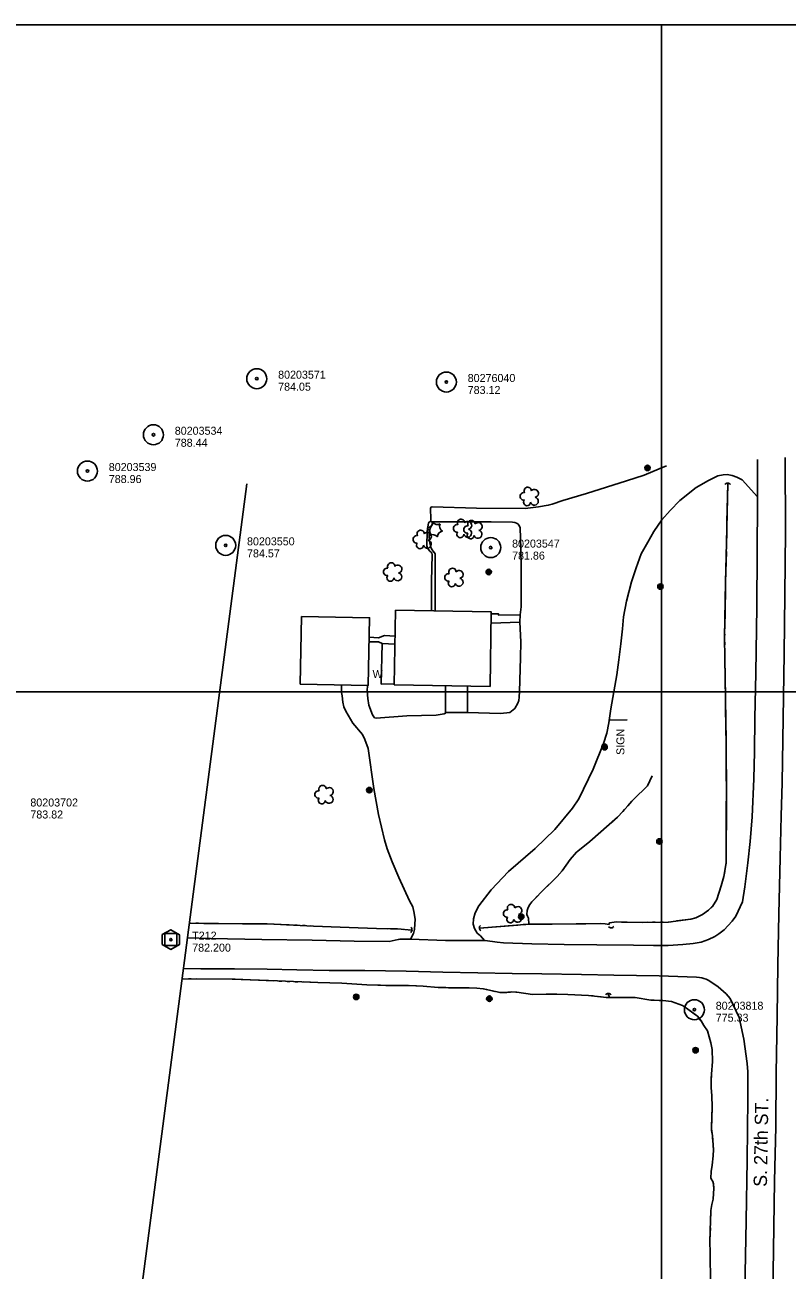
# Model space of a CAD drawing. Extents: x 591954 to 597000, y 198576 to 213500.
# Drawn here: x 593523 to 594094, y 212566 to 213500 of the extents above; entities that cross this region are included whole.
import ezdxf

# ---------------------------------------------------------------- set-up
doc = ezdxf.new("R2010")
doc.units = 0
for name, color, linetype in [('1', 7, 'Continuous'), ('Level 10', 7, 'Continuous'), ('Level 11', 7, 'Continuous'), ('Level 12', 7, 'Continuous'), ('Level 14', 7, 'Continuous'), ('Level 15', 7, 'Continuous'), ('Level 17', 7, 'Continuous'), ('Level 18', 7, 'Continuous'), ('Level 19', 7, 'Continuous'), ('Level 29', 7, 'Continuous'), ('Level 4', 7, 'Continuous'), ('Level 5', 7, 'Continuous'), ('Level 6', 7, 'Continuous')]:
    doc.layers.add(name, color=color, linetype=linetype)

msp = doc.modelspace()

# ---------------------------------------------------------------- linework, layer by layer
at = {"layer": 'Level 10'}
for p, q in [((593000, 213500), (595000, 213500)), ((594000, 212000), (594000, 213500)), ((593000, 213000), (595000, 213000))]:
    msp.add_line(p, q, dxfattribs=at)
at = {"layer": 'Level 11'}
for points in [[(594071.8, 213146.24), (594071.99, 213174.06)], [(594092.68, 213175.51), (594092.9, 213119.81), (594092.29, 213072.65), (594091.97, 213028.51), (594090.27, 212931.76), (594089.7, 212906.93), (594088.86, 212875.4), (594087.84, 212833.27), (594087.14, 212794.98), (594086.66, 212756.81), (594085.93, 212713.94), (594085.53, 212673.64), (594084.73, 212633.12), (594084.11, 212598.75), (594083.6, 212564.55), (594083.15, 212537.46), (594082.82, 212511.46), (594081.98, 212463.34), (594080.88, 212411.88), (594080.18, 212370.87), (594079.33, 212335.57), (594078.5, 212299.63), (594077.69, 212261.21)], [(593867.34, 212813.52), (593867.74, 212813.52), (593876.85, 212812.15), (593881.45, 212811.68), (593902.84, 212810.93), (593926.97, 212810.5), (593951.36, 212810.27), (593979.06, 212809.93), (593993.98, 212809.78), (594004.98, 212809.74), (594016, 212810.56), (594023.64, 212811.19), (594029.62, 212812.3), (594035.15, 212814.31), (594040, 212816.46), (594042.92, 212818.49), (594046.81, 212821.57), (594052.9, 212827.99), (594055.72, 212831.67), (594060.58, 212842.45), (594062.44, 212853.72), (594064.74, 212871.68), (594066.41, 212887.58), (594067.84, 212906.27), (594069.16, 212934.57), (594069.56, 212954.94), (594069.92, 212980.15), (594070.59, 213013.89), (594071.47, 213063.73), (594071.73, 213103.98), (594071.78, 213143.2), (594071.8, 213146.24)], [(593644.66, 212815.5), (593661.85, 212815.09), (593700.41, 212814.29), (593738.06, 212813.73), (593769.47, 212813.01), (593795.9, 212812.79), (593802.64, 212814.18), (593804.04, 212814.52), (593805.93, 212814.57), (593811.71, 212814.48)], [(593811.71, 212814.48), (593837.94, 212813.49), (593867.34, 212813.52)], [(594062.39, 212551.08), (594063.31, 212603.36), (594064.13, 212648.72), (594064.57, 212694.79), (594064.68, 212709.98), (594064.57, 212715.11), (594064.04, 212721.15), (594061.78, 212739.41), (594058.15, 212755.76), (594051.39, 212769.97), (594048.32, 212773.56), (594042.39, 212778.73), (594037.01, 212782.5), (594034.82, 212783.72), (594033.43, 212784.35), (594031.76, 212785.06), (594030.25, 212785.44), (594028.4, 212785.7), (594026.26, 212785.86), (593998.27, 212786.99), (593964.23, 212787.37), (593940.05, 212787.94), (593910.2, 212788.39), (593888, 212788.76), (593862.21, 212789.1), (593836.02, 212789.75), (593808.47, 212790.37), (593777.54, 212790.97), (593750.93, 212791.08), (593726.61, 212791.42), (593704.37, 212791.9), (593679.9, 212792.13), (593654.64, 212792.32), (593641.66, 212792.57)]]:
    msp.add_lwpolyline(points, dxfattribs=at)
at = {"layer": 'Level 12'}
for points in [[(593730.19, 213056.46), (593729.15, 213005.79), (593780.14, 213004.74), (593781.18, 213055.41), (593730.19, 213056.46)], [(593799.66, 213005.1), (593871.45, 213003.94), (593872.35, 213059.88), (593800.57, 213061.04), (593799.66, 213005.1)], [(593893.92, 213057.76), (593877.77, 213057.53), (593877.73, 213058.42), (593872.33, 213058.35)]]:
    msp.add_lwpolyline(points, dxfattribs=at)
at = {"layer": 'Level 14'}
msp.add_lwpolyline([(593974.27, 212978.92), (593960.4, 212978.7)], dxfattribs=at)
for centre, radius in [((593989.45, 213167.79), 2.02), ((593989.45, 213167.8), 1.52), ((593989.46, 213167.76), 1.01), ((593989.46, 213167.77), 0.502), ((593870.46, 213089.79), 2.02), ((593870.46, 213089.8), 1.52), ((593870.47, 213089.76), 1.01), ((593870.47, 213089.77), 0.502), ((593999.18, 213078.85), 2.02), ((593999.17, 213078.86), 1.52), ((593999.18, 213078.82), 1.01), ((593999.18, 213078.83), 0.502), ((593957.21, 212958.73), 2.02), ((593957.29, 212958.34), 2.02), ((593957.21, 212958.74), 1.52), ((593957.28, 212958.35), 1.52), ((593957.22, 212958.7), 1.01), ((593957.29, 212958.31), 1.01), ((593957.22, 212958.71), 0.502), ((593957.29, 212958.32), 0.502), ((593780.94, 212926.21), 2.02), ((593780.94, 212926.22), 1.52), ((593780.95, 212926.18), 1.01), ((593780.95, 212926.19), 0.502), ((593998.4, 212887.74), 2.02), ((593998.4, 212887.76), 1.52), ((593998.41, 212887.72), 1.01), ((593998.41, 212887.73), 0.502), ((593894.79, 212831.3), 2.02), ((593894.78, 212831.32), 1.52), ((593894.79, 212831.28), 1.01), ((593894.79, 212831.29), 0.502), ((593771.11, 212771.19), 2.02), ((593771.1, 212771.2), 1.52), ((593771.11, 212771.16), 1.01), ((593771.11, 212771.17), 0.502), ((593870.92, 212769.84), 2.02), ((593870.92, 212769.86), 1.52), ((593870.92, 212769.82), 1.01), ((593870.93, 212769.83), 0.502), ((594025.48, 212731.21), 2.02), ((594025.48, 212731.23), 1.52), ((594025.48, 212731.19), 1.01), ((594025.49, 212731.2), 0.502)]:
    msp.add_circle(centre, radius, dxfattribs=at)
at = {"layer": 'Level 15'}
msp.add_lwpolyline([(593800.16, 213035.73), (593790.51, 213036.24), (593789.93, 213005.78), (593799.67, 213005.81)], dxfattribs=at)
for centre, start, end in [((594049.57, 213153.87), 35.87943, 142.11899), ((593810.45, 212821.47), 304.27944, 50.519), ((593865.88, 212822.81), 128.97943, 235.21899), ((593962.13, 212825.42), 220.27943, 326.51899), ((593960.12, 212771.21), 37.27942, 143.51898)]:
    msp.add_arc(centre, 2.5, start, end, dxfattribs=at)
at = {"layer": 'Level 17'}
for points in [[(593827.16, 213128.06), (593827.14, 213129.23), (593826.89, 213137.72), (593827.33, 213138.43), (593828.08, 213138.55), (593861.39, 213137.69), (593897.8, 213137.49), (593907.78, 213138.74), (593915.09, 213139.8), (593918.09, 213140.54), (593926.03, 213143.31), (593943.8, 213148.67), (593973.82, 213158.03), (593986.88, 213162.47), (593998.08, 213167.05), (594003.62, 213169.36)], [(593827.16, 213128.06), (593825.33, 213126.65), (593824.24, 213120.17), (593824.03, 213109.33), (593824.58, 213107.9), (593825.02, 213106.9), (593826.61, 213105.27), (593827.42, 213104.58), (593827.86, 213103.9), (593828.16, 213102.78), (593827.51, 213082.56), (593827.66, 213060.6)], [(593830.33, 213060.56), (593830.18, 213075.76), (593830.29, 213102.89), (593830.19, 213103.5), (593829.8, 213104.21), (593828.71, 213105.52), (593828.09, 213106.49), (593827.16, 213108.15), (593825.96, 213112.85), (593825.82, 213116.79), (593825.9, 213120.4), (593826.23, 213121.72), (593826.83, 213123.16), (593829.24, 213127.37)], [(593829.24, 213127.37), (593827.41, 213127.32), (593827.16, 213128.06)], [(593893.77, 213052.17), (593893.92, 213057.76), (593894.71, 213063.54), (593894.76, 213070.24), (593894.66, 213093.79), (593894.49, 213107.14), (593893.97, 213122.83), (593893.18, 213124.69), (593892.18, 213125.95), (593891.3, 213126.47), (593889.97, 213127), (593888.19, 213127.04), (593872.32, 213127.37), (593853.77, 213127.35), (593829.24, 213127.37)], [(593854.42, 212984.34), (593879.25, 212983.72), (593886.25, 212984.34), (593890.06, 212987.48), (593892.15, 212991.31), (593892.92, 212993.48), (593893.35, 212995.81), (593893.61, 213000.09), (593894.33, 213025.54), (593894.47, 213037.35), (593893.77, 213052.17)], [(593872.21, 213051.35), (593893.77, 213052.17)], [(593790.51, 213036.24), (593787.88, 213037.35), (593780.81, 213037.34)], [(593780.88, 213040.98), (593787.86, 213040.52), (593792.32, 213042.2), (593800.26, 213041.73)], [(593811.71, 212814.48), (593814.11, 212818.77), (593814.83, 212821.66), (593815.15, 212825.87), (593815.23, 212829.32), (593814.59, 212833.9), (593813.47, 212838.71), (593810.98, 212843.19), (593802.99, 212860.8), (593798, 212872.56), (593794.24, 212882.12), (593792.37, 212889.04), (593787.94, 212907.96), (593784.24, 212927.39), (593780.07, 212957.37), (593777.61, 212964.16), (593775.82, 212968), (593768.68, 212976.4), (593763.45, 212985.34), (593761.9, 212988.69), (593760.97, 212992.23), (593760.47, 212996.96), (593760.2, 212999.31), (593760.21, 213005.15)], [(593779.53, 213004.75), (593779.42, 213000.62), (593779.82, 212995.02), (593780.68, 212989.87), (593783.45, 212982.68), (593784.23, 212981.18), (593784.93, 212980.46), (593786.05, 212980.23), (593809.06, 212982.03), (593831.04, 212982.31), (593837.11, 212983.31), (593838.08, 212983.99), (593838.64, 212984.43)], [(593838.64, 212984.43), (593838.03, 212984.43), (593837.96, 213004.48)], [(593854.42, 212984.34), (593854.46, 213004.22)], [(593838.64, 212984.43), (593853.89, 212984.35), (593854.42, 212984.34)]]:
    msp.add_lwpolyline(points, dxfattribs=at)
at = {"layer": 'Level 18'}
for centre, radius, start, end in [((593896.71, 213146.51), 2.78, 78.07156, 279.08261), ((593899.71, 213150.59), 2.78, 1.39455, 209.16754), ((593904.75, 213148.73), 2.97, 278.42366, 139.65754), ((593899.17, 213142.11), 2.61, 140.77971, 358.71232), ((593904.64, 213142.88), 2.97, 196.07448, 79.04774), ((593849.7, 213126.6), 2.78, 1.39455, 209.16754), ((593819.47, 213118.34), 2.78, 1.39455, 209.16754), ((593824, 213127.1), 4.3, 275.21132, 0.97623), ((593822.31, 213119.05), 4.3, 335.21132, 60.97623), ((593831.82, 213129.65), 4.3, 215.21132, 300.97623), ((593836.24, 213116.11), 4.3, 95.21133, 180.97624), ((593837.94, 213124.16), 4.3, 155.21133, 240.97624), ((593846.7, 213122.52), 2.78, 78.07156, 279.08261), ((593849.16, 213118.12), 2.61, 140.77971, 358.71232), ((593854.46, 213121.63), 2.78, 78.07156, 279.08261), ((593854.63, 213118.89), 2.97, 196.07448, 79.04774), ((593854.74, 213124.74), 2.97, 278.42366, 139.65754), ((593857.46, 213125.7), 2.78, 1.39455, 209.16754), ((593862.39, 213117.99), 2.97, 196.07448, 79.04774), ((593862.5, 213123.85), 2.97, 278.42366, 139.65754), ((593816.47, 213114.26), 2.78, 78.07156, 279.08261), ((593818.93, 213109.86), 2.61, 140.77971, 358.71232), ((593824.4, 213110.62), 2.97, 196.07448, 79.04774), ((593824.51, 213116.48), 2.97, 278.42366, 139.65754), ((593828.42, 213113.56), 4.3, 35.21133, 120.97624), ((593856.92, 213117.23), 2.61, 140.77971, 358.71232), ((593794.33, 213089.84), 2.78, 78.07156, 279.08261), ((593797.33, 213093.91), 2.78, 1.39455, 209.16754), ((593802.37, 213092.06), 2.97, 278.42366, 139.65754), ((593843.27, 213089.81), 2.78, 1.39455, 209.16754), ((593796.79, 213085.44), 2.61, 140.77971, 358.71232), ((593802.26, 213086.2), 2.97, 196.07448, 79.04774), ((593840.27, 213085.73), 2.78, 78.07156, 279.08261), ((593842.73, 213081.33), 2.61, 140.77971, 358.71232), ((593848.2, 213082.1), 2.97, 196.07448, 79.04774), ((593848.31, 213087.95), 2.97, 278.42366, 139.65754), ((593742.86, 212922.94), 2.78, 78.07156, 279.08261), ((593745.86, 212927.01), 2.78, 1.39455, 209.16754), ((593750.9, 212925.15), 2.97, 278.42366, 139.65754), ((593745.32, 212918.54), 2.61, 140.77971, 358.71232), ((593750.79, 212919.3), 2.97, 196.07448, 79.04774), ((593887.2, 212837.79), 2.78, 1.39455, 209.16754), ((593884.2, 212833.71), 2.78, 78.07156, 279.08261), ((593886.66, 212829.32), 2.61, 140.77971, 358.71232), ((593892.13, 212830.08), 2.97, 196.07448, 79.04774), ((593892.24, 212835.93), 2.97, 278.42366, 139.65754)]:
    msp.add_arc(centre, radius, start, end, dxfattribs=at)
at = {"layer": 'Level 19'}
for points in [[(594049.59, 213156.18), (594048.74, 213111.67), (594048.03, 213082.12), (594047.27, 213040.69), (594048.02, 212994.11), (594048.31, 212963.43), (594048.56, 212920.3), (594048.37, 212871.67), (594046.77, 212861.49), (594044.76, 212854.41), (594041.46, 212844.33), (594038.08, 212838.99), (594035.11, 212836.12), (594030.72, 212832.88), (594025.74, 212830.56), (594021.81, 212829.51), (594004.85, 212827.24), (593985.72, 212827.05), (593974.28, 212827.1), (593969.89, 212827.25), (593966.13, 212827.37), (593960.94, 212826.65), (593960.77, 212825.5)], [(594049.59, 213156.18), (594049.04, 213127.19)], [(594048.96, 213123.19), (594048.92, 213121.19)], [(594048.72, 213111.19), (594048.68, 213109.19)], [(594048.84, 213117.19), (594048.8, 213115.19)], [(594048.58, 213105.19), (594048.03, 213082.12), (594047.92, 213076.2)], [(594047.92, 213076.2), (594047.39, 213047.2)], [(594047.31, 213043.2), (594047.28, 213041.21)], [(594047.32, 213037.21), (594047.35, 213035.21)], [(594047.42, 213031.21), (594047.45, 213029.21)], [(594047.52, 213025.21), (594047.99, 212996.21)], [(594047.99, 212996.21), (594048.02, 212994.11), (594048.27, 212967.21)], [(594048.31, 212963.21), (594048.32, 212961.21)], [(594048.34, 212957.21), (594048.35, 212955.21)], [(594048.38, 212951.21), (594048.39, 212949.21)], [(594048.41, 212945.21), (594048.56, 212920.3), (594048.54, 212916.21)], [(593992.96, 212936.82), (593989.38, 212929.45), (593986.34, 212926.35), (593982.05, 212922.18), (593977.81, 212917.97), (593974.62, 212914.5), (593970.97, 212910.16), (593967.06, 212905.94), (593946.14, 212887.62), (593936.2, 212879.65), (593931.48, 212874.15), (593925.51, 212865.73), (593921.74, 212861.38), (593910.27, 212850.21), (593905.66, 212845.55), (593902.82, 212842.4), (593901.3, 212840.34), (593899.94, 212838.11), (593899.15, 212835.94), (593898.99, 212833.08), (593899.6, 212831.63), (593900.19, 212830.29), (593900.55, 212825.7)], [(593974.76, 212914.66), (593977.81, 212917.97), (593982.05, 212922.18), (593986.34, 212926.35), (593989.38, 212929.45), (593992.96, 212936.82)], [(594048.54, 212916.21), (594048.43, 212887.21)], [(593966.79, 212905.7), (593967.06, 212905.94), (593968.17, 212907.14)], [(593970.89, 212910.07), (593970.97, 212910.16), (593972.18, 212911.6)], [(593937.12, 212880.39), (593946.14, 212887.62), (593959.26, 212899.11)], [(593962.27, 212901.74), (593963.78, 212903.06)], [(593918.52, 212858.25), (593921.74, 212861.38), (593925.51, 212865.73), (593931.48, 212874.15), (593936.2, 212879.65), (593937.12, 212880.39)], [(594048.39, 212877.21), (594048.39, 212875.21)], [(594048.42, 212883.21), (594048.41, 212881.21)], [(594048.3, 212871.22), (594047.99, 212869.24)], [(594047.37, 212865.29), (594046.77, 212861.49), (594044.76, 212854.41), (594041.46, 212844.33), (594038.08, 212838.99), (594037.45, 212838.39)], [(593909.93, 212849.87), (593910.27, 212850.21), (593911.36, 212851.27)], [(593914.22, 212854.06), (593915.66, 212855.46)], [(593900.55, 212825.7), (593900.19, 212830.29), (593899.6, 212831.63), (593898.99, 212833.08), (593899.15, 212835.94), (593899.94, 212838.11), (593901.3, 212840.34), (593902.82, 212842.4), (593903.03, 212842.63)], [(593905.71, 212845.6), (593907.12, 212847.02)], [(594037.45, 212838.39), (594035.11, 212836.12), (594030.72, 212832.88), (594025.74, 212830.56), (594021.81, 212829.51), (594011.19, 212828.09)], [(593646.09, 212826.49), (593667.8, 212826.09), (593704.44, 212825.96), (593739.17, 212824.3), (593759.14, 212823.55), (593786.45, 212822.47), (593796.77, 212822.13), (593802.11, 212822.1), (593812.81, 212821.24)], [(593646.87, 212826.48), (593646.09, 212826.49)], [(593652.86, 212826.37), (593650.86, 212826.4)], [(593685.86, 212826.02), (593667.8, 212826.09), (593656.86, 212826.29)], [(593714.85, 212825.46), (593704.44, 212825.96), (593685.86, 212826.02)], [(593720.84, 212825.17), (593718.84, 212825.27)], [(593726.84, 212824.89), (593724.84, 212824.98)], [(593732.83, 212824.6), (593730.83, 212824.7)], [(593765.8, 212823.29), (593759.14, 212823.55), (593739.17, 212824.3), (593736.83, 212824.41)], [(593794.78, 212822.2), (593786.45, 212822.47), (593765.8, 212823.29)], [(593800.78, 212822.11), (593798.78, 212822.12)], [(593806.77, 212821.73), (593804.77, 212821.89)], [(593812.75, 212821.25), (593810.75, 212821.41)], [(593863.45, 212822.78), (593900.55, 212825.7), (593917.99, 212825.71), (593953.88, 212826.1), (593957.75, 212825.9), (593959.29, 212825.66), (593960.77, 212825.5)], [(593892.37, 212825.05), (593863.45, 212822.78)], [(593898.35, 212825.52), (593896.35, 212825.37)], [(593904.34, 212825.7), (593902.34, 212825.7)], [(593910.34, 212825.7), (593908.34, 212825.7)], [(593943.34, 212825.98), (593917.99, 212825.71), (593914.34, 212825.7)], [(593960.77, 212825.5), (593959.29, 212825.66), (593957.75, 212825.9), (593953.88, 212826.1), (593943.34, 212825.98)], [(593960.84, 212826.02), (593960.77, 212825.5)], [(593989.24, 212827.09), (593985.72, 212827.05), (593974.28, 212827.1), (593969.89, 212827.25), (593966.13, 212827.37), (593960.94, 212826.65), (593960.84, 212826.02)], [(593995.24, 212827.15), (593993.24, 212827.13)], [(594001.24, 212827.21), (593999.24, 212827.19)], [(594007.22, 212827.56), (594005.24, 212827.3)], [(593640.65, 212784.78), (593678.26, 212784.56), (593712.01, 212783.11), (593742.36, 212781.91), (593760.45, 212781.5), (593778.98, 212780.17), (593795.3, 212779.71), (593810.33, 212779.68), (593821.23, 212779.22), (593832.66, 212778.25), (593838.19, 212778.12), (593855.7, 212777.94), (593861.48, 212777.79), (593866.3, 212777.3), (593879.03, 212774.39), (593884.05, 212774.6), (593887.4, 212774.88), (593891.6, 212774.78), (593903.14, 212773.04), (593913.58, 212773.22), (593916.91, 212773.31), (593921.54, 212773.31), (593929.66, 212773.09), (593945.14, 212772.32), (593949.74, 212771.8), (593956.35, 212771.02), (593959.62, 212770.63), (593960.87, 212770.68), (593975.67, 212770.71), (593980.26, 212770.63), (593992.03, 212768.65), (593994.5, 212768.61), (593998.12, 212768.52), (594000.87, 212768.52), (594007.45, 212767.85), (594015.77, 212764.84), (594018.78, 212762.66), (594027, 212756.62), (594029.56, 212753.14), (594031.76, 212749.79), (594034.34, 212745.73), (594037, 212736.65), (594037.84, 212731.74), (594038.11, 212722.7), (594037.45, 212713.2), (594037.05, 212707.74), (594037.22, 212702.92), (594037.57, 212697.13), (594037.99, 212688.51), (594037.31, 212672.15), (594038.06, 212666.93), (594038.82, 212656.85), (594038.77, 212651.99), (594037.84, 212644.98), (594037.18, 212640.32), (594036.94, 212635.31), (594038.77, 212632.19), (594039.06, 212627.79), (594038.57, 212619.55), (594037.66, 212615.59), (594036.9, 212611.06), (594036.54, 212595.69), (594036.17, 212587.51), (594036.33, 212579.57)], [(593640.65, 212784.78), (593641.36, 212784.78)], [(593645.36, 212784.76), (593647.36, 212784.74)], [(593651.36, 212784.72), (593678.26, 212784.56), (593680.36, 212784.47)], [(593680.36, 212784.47), (593709.33, 212783.23)], [(593713.33, 212783.06), (593715.33, 212782.98)], [(593719.33, 212782.82), (593721.32, 212782.74)], [(593725.32, 212782.59), (593727.32, 212782.51)], [(593731.32, 212782.35), (593742.36, 212781.91), (593760.3, 212781.51)], [(593760.3, 212781.51), (593760.45, 212781.5), (593778.98, 212780.17), (593789.25, 212779.88)], [(593793.25, 212779.77), (593795.25, 212779.71)], [(593799.25, 212779.7), (593801.25, 212779.7)], [(593805.25, 212779.69), (593807.25, 212779.68)], [(593811.25, 212779.64), (593821.23, 212779.22), (593832.66, 212778.25), (593838.19, 212778.12), (593840.2, 212778.1)], [(593840.2, 212778.1), (593855.7, 212777.94), (593861.48, 212777.79), (593866.3, 212777.3), (593869.1, 212776.66)], [(593872.99, 212775.77), (593874.95, 212775.32)], [(593878.84, 212774.43), (593879.03, 212774.39), (593880.84, 212774.46)], [(593884.83, 212774.66), (593886.83, 212774.83)], [(593890.82, 212774.8), (593891.6, 212774.78), (593903.14, 212773.04), (593913.58, 212773.22), (593916.91, 212773.31), (593919.69, 212773.31)], [(593919.69, 212773.31), (593921.54, 212773.31), (593929.66, 212773.09), (593945.14, 212772.32), (593948.64, 212771.92)], [(593952.62, 212771.46), (593954.6, 212771.22)], [(593958.58, 212770.75), (593959.62, 212770.63), (593960.57, 212770.67)], [(593960.06, 212773.42), (593960.87, 212770.68)], [(593960.06, 212773.42), (593960.87, 212770.68)], [(593964.57, 212770.69), (593966.57, 212770.69)], [(593970.57, 212770.7), (593975.67, 212770.71), (593980.26, 212770.63), (593992.03, 212768.65), (593994.5, 212768.61), (593998.12, 212768.52), (593999.4, 212768.52)], [(593999.4, 212768.52), (594000.87, 212768.52), (594007.45, 212767.85), (594015.77, 212764.84), (594018.78, 212762.66), (594025.51, 212757.71)], [(594028.28, 212754.89), (594029.46, 212753.28)], [(594031.66, 212749.94), (594031.76, 212749.79), (594032.74, 212748.25)], [(594034.63, 212744.76), (594035.19, 212742.84)], [(594036.31, 212739), (594037, 212736.65), (594037.84, 212731.74), (594038.11, 212722.7), (594037.45, 212713.2), (594037.23, 212710.21)], [(594037.23, 212710.21), (594037.05, 212707.74), (594037.22, 212702.92), (594037.57, 212697.13), (594037.99, 212688.51), (594037.69, 212681.24)], [(594037.52, 212677.25), (594037.44, 212675.25)], [(594037.44, 212671.26), (594037.72, 212669.28)], [(594038.18, 212665.31), (594038.33, 212663.32)], [(594038.63, 212659.33), (594038.82, 212656.85), (594038.77, 212651.99), (594037.84, 212644.98), (594037.18, 212640.32), (594036.94, 212635.31), (594038.77, 212632.19), (594038.85, 212630.95)], [(594038.85, 212630.95), (594039.06, 212627.79), (594038.57, 212619.55), (594037.66, 212615.59), (594036.9, 212611.06), (594036.69, 212602.14)], [(594036.6, 212598.14), (594036.55, 212596.14)], [(594036.38, 212592.14), (594036.29, 212590.15)], [(594036.33, 212579.57), (594036.74, 212556.45), (594036.54, 212528.17), (594036.4, 212501.64), (594035.69, 212471.43), (594034.85, 212449.06), (594035.58, 212427.12), (594034.85, 212411.93), (594034.15, 212409.48), (594033.78, 212403.72), (594033.66, 212400.05), (594033.4, 212397.46), (594033.55, 212392.66), (594033.67, 212387.69), (594033.2, 212381.87), (594032.9, 212374.88), (594032.9, 212369.77), (594032.69, 212361.54), (594032.97, 212348.75), (594033.37, 212341.77), (594033.84, 212339.96), (594035.84, 212336.65)], [(594036.19, 212586.15), (594036.23, 212584.15)], [(594036.32, 212580.15), (594036.33, 212579.57)], [(594036.33, 212579.57), (594036.74, 212556.45), (594036.7, 212550.57)]]:
    msp.add_lwpolyline(points, dxfattribs=at)
at = {"layer": 'Level 29'}
msp.add_lwpolyline([(594071.8, 213146.24), (594060.43, 213158.84), (594056.49, 213160.79), (594053, 213162.03), (594049.12, 213162.77), (594046.23, 213162.71), (594042.29, 213161.76), (594035.14, 213158.45), (594025.9, 213153.12), (594013.72, 213143.27), (594006.37, 213135.97), (594000.1, 213128.84), (593994.08, 213120.15), (593989.6, 213112.07), (593984.72, 213103.43), (593981.06, 213092.85), (593977.58, 213082.46), (593973.73, 213067.9), (593971.4, 213056.05), (593970.69, 213047.04), (593969.35, 213035.9), (593968.05, 213023.85), (593966.47, 213012.58), (593962.05, 212987.15), (593960.5, 212976.72), (593959.08, 212968.89), (593956.51, 212961.13), (593948.7, 212941.82), (593937.88, 212919.79), (593933.23, 212912.73), (593920.11, 212896.63), (593905.27, 212882.57), (593885.33, 212865.17), (593872.17, 212851.54), (593862.97, 212839.4), (593860.24, 212834.17), (593858.98, 212829.78), (593858.85, 212825.68), (593859.83, 212822.34), (593861.78, 212819.05), (593864.21, 212816.98), (593867.34, 212813.52)], dxfattribs=at)
at = {"layer": 'Level 4'}
msp.add_lwpolyline([(593594.56, 212431.65), (593689.09, 213155.98)], dxfattribs=at)
at = {"layer": 'Level 5'}
for points in [[(593625.77, 212817.88), (593625.77, 212810.49), (593632.23, 212806.77), (593638.62, 212810.43), (593638.62, 212817.76), (593632.1, 212821.49)], [(593627.68, 212809.62), (593627.68, 212818.62), (593636.68, 212818.62), (593636.68, 212809.62)]]:
    msp.add_lwpolyline(points, close=True, dxfattribs=at)
msp.add_circle((593632.18, 212814.12), 0.871, dxfattribs=at)
at = {"layer": 'Level 6'}
for centre, radius in [((593696.59, 213234.72), 7.5), ((593696.59, 213234.72), 0.96), ((593838.69, 213232.24), 7.5), ((593838.69, 213232.24), 0.96), ((593619.13, 213192.69), 7.5), ((593619.13, 213192.69), 0.96), ((593569.66, 213165.47), 7.5), ((593569.66, 213165.47), 0.96), ((593673.28, 213109.76), 7.5), ((593673.28, 213109.76), 0.96), ((593871.96, 213108.08), 7.5), ((593871.96, 213108.08), 0.96), ((594024.61, 212761.57), 7.5), ((594024.61, 212761.57), 0.96)]:
    msp.add_circle(centre, radius, dxfattribs=at)

# ---------------------------------------------------------------- texts
at = {"layer": '1'}
msp.add_text('S. 27th ST.', height=10, rotation=88.99841, dxfattribs=at).set_placement((594078.95, 212628.7))
at = {"layer": 'Level 14'}
msp.add_text('SIGN', height=6, rotation=90, dxfattribs=at).set_placement((593972.13, 212952.61))
at = {"layer": 'Level 15'}
msp.add_text('W', height=6, dxfattribs=at).set_placement((593783.39, 213010.2))
at = {"layer": 'Level 5'}
for s, p in [('T212', (593648.18, 212814.12)), ('782.200', (593648.18, 212805.12))]:
    msp.add_text(s, height=6, dxfattribs=at).set_placement(p)
at = {"layer": 'Level 6'}
for s, p in [('80203571', (593712.59, 213234.72)), ('784.05', (593712.59, 213225.72)), ('80276040', (593854.69, 213232.24)), ('783.12', (593854.69, 213223.24)), ('80203534', (593635.13, 213192.69)), ('788.44', (593635.13, 213183.69)), ('80203539', (593585.66, 213165.47)), ('788.96', (593585.66, 213156.47)), ('80203550', (593689.28, 213109.76)), ('80203547', (593887.96, 213108.08)), ('784.57', (593689.28, 213100.76)), ('781.86', (593887.96, 213099.08)), ('80203702', (593526.88, 212913.95)), ('783.82', (593526.88, 212904.95)), ('80203818', (594040.61, 212761.57)), ('775.33', (594040.61, 212752.57))]:
    msp.add_text(s, height=6, dxfattribs=at).set_placement(p)

doc.saveas('drawing.dxf')
